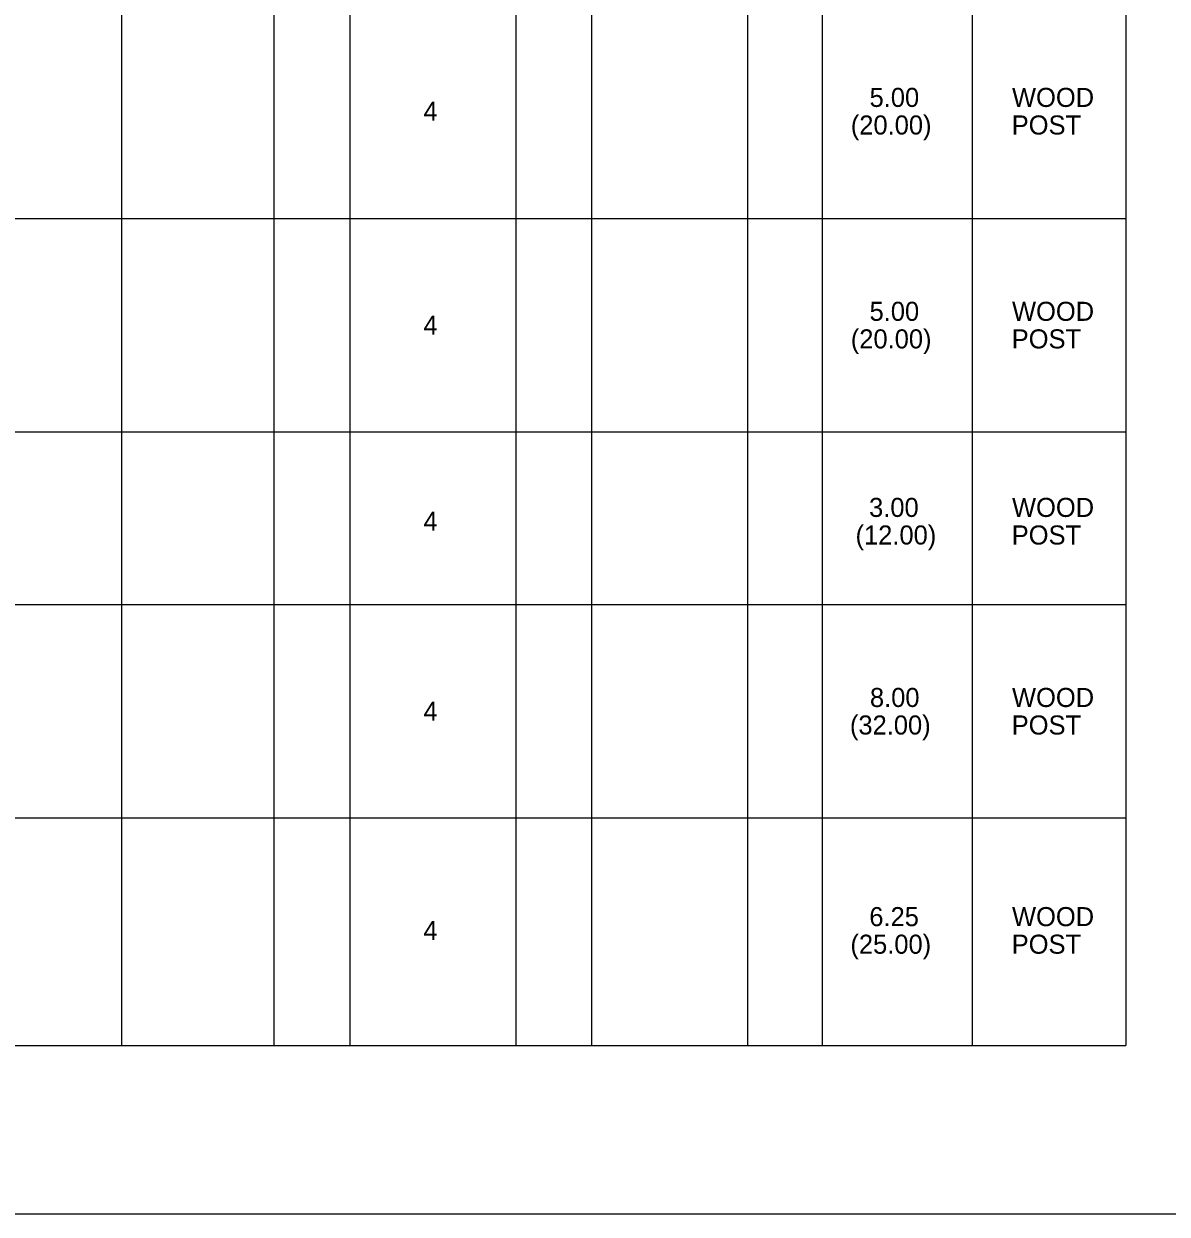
# Model space of a CAD drawing. Extents: x 914742 to 915492, y 328736 to 329423.
# Drawn here: x 914929.2 to 915116.7, y 328898.3 to 329093.4 of the extents above; entities that cross this region are included whole.
import ezdxf

# ---------------------------------------------------------------- set-up
doc = ezdxf.new("R2010")
doc.units = 0
for name, color, linetype in [('ANNOTATION', 7, 'Continuous'), ('PLOT BOUNDARY', 7, 'Continuous'), ('SIGNSUM-TABLE', 7, 'Continuous')]:
    doc.layers.add(name, color=color, linetype=linetype)

msp = doc.modelspace()

# ---------------------------------------------------------------- linework, layer by layer
at = {"layer": 'ANNOTATION'}
for p, q in [((914945.2, 329346.26), (914945.2, 328925.96)), ((914970.17, 329346.26), (914970.17, 328925.96)), ((915022.25, 329346.26), (915022.25, 328925.96)), ((915047.87, 329346.26), (915047.87, 328925.96)), ((914945.2, 329311.41), (914945.2, 328925.96)), ((914970.17, 329311.41), (914970.17, 328925.96)), ((915022.25, 329311.41), (915022.25, 328925.96)), ((915047.87, 329311.41), (915047.87, 328925.96))]:
    msp.add_line(p, q, dxfattribs=at)
at = {"layer": 'PLOT BOUNDARY'}
msp.add_lwpolyline([(915491.67, 328898.32), (914741.67, 328898.32), (914741.67, 329423.32), (915491.67, 329423.32)], close=True, dxfattribs=at)
at = {"layer": 'SIGNSUM-TABLE'}
for p, q in [((914982.66, 328925.96), (914982.66, 329404.01)), ((914982.66, 328925.96), (914982.66, 329404.01)), ((915009.92, 328925.96), (915009.92, 329404.01)), ((915009.92, 328925.96), (915009.92, 329404.01)), ((915060.15, 328925.96), (915060.15, 329404.01)), ((915060.15, 328925.96), (915060.15, 329404.01)), ((915084.76, 328925.96), (915084.76, 329404.01)), ((915084.76, 328925.96), (915084.76, 329404.01)), ((915109.88, 329404.01), (915109.88, 328925.96)), ((915109.88, 329404.01), (915109.88, 328925.96)), ((914748.46, 329061.54), (915109.88, 329061.54)), ((914748.46, 329061.54), (915109.88, 329061.54)), ((914748.46, 329026.54), (915109.88, 329026.54)), ((914748.46, 329026.54), (915109.88, 329026.54)), ((914748.46, 328998.26), (915109.88, 328998.26)), ((914748.46, 328963.26), (915109.88, 328963.26)), ((914748.46, 328925.96), (915109.88, 328925.96))]:
    msp.add_line(p, q, dxfattribs=at)

# ---------------------------------------------------------------- texts
at = {"layer": 'ANNOTATION'}
for s, height, p in [('5.00', 3.125, (915067.86, 329079.8)), ('WOOD', 3.125, (915091.22, 329079.8)), ('4', 3.12, (914994.7, 329077.54)), ('(20.00)', 3.125, (915064.78, 329075.28)), ('POST', 3.125, (915091.17, 329075.28)), ('5.00', 3.125, (915067.86, 329044.74)), ('WOOD', 3.125, (915091.22, 329044.74)), ('4', 3.12, (914994.7, 329042.48)), ('(20.00)', 3.125, (915064.78, 329040.22)), ('POST', 3.125, (915091.17, 329040.22)), ('3.00', 3.125, (915067.78, 329012.6)), ('WOOD', 3.125, (915091.22, 329012.6)), ('4', 3.12, (914994.7, 329010.34)), ('(12.00)', 3.125, (915065.56, 329008.08)), ('POST', 3.125, (915091.17, 329008.08)), ('8.00', 3.125, (915067.92, 328981.45)), ('WOOD', 3.125, (915091.22, 328981.45)), ('4', 3.12, (914994.7, 328979.2)), ('(32.00)', 3.125, (915064.64, 328976.94)), ('POST', 3.125, (915091.17, 328976.94)), ('6.25', 3.125, (915067.82, 328945.53)), ('WOOD', 3.125, (915091.22, 328945.53)), ('4', 3.12, (914994.7, 328943.27)), ('(25.00)', 3.125, (915064.72, 328941.01)), ('POST', 3.125, (915091.17, 328941.01))]:
    msp.add_text(s, height=height, dxfattribs=at).set_placement(p)

doc.saveas('drawing.dxf')
